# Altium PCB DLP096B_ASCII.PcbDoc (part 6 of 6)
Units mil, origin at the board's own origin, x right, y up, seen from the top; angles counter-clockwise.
Board outline 4950 x 3159.45 mil, 8 copper layers (Top Layer, GND1, SIGNAL1, POWER1, POWER2, SIGNAL2, GND2, Bottom Layer), stack 60.4 mil thick; 327 components, 222 nets, 1374 pads, 853 vias.
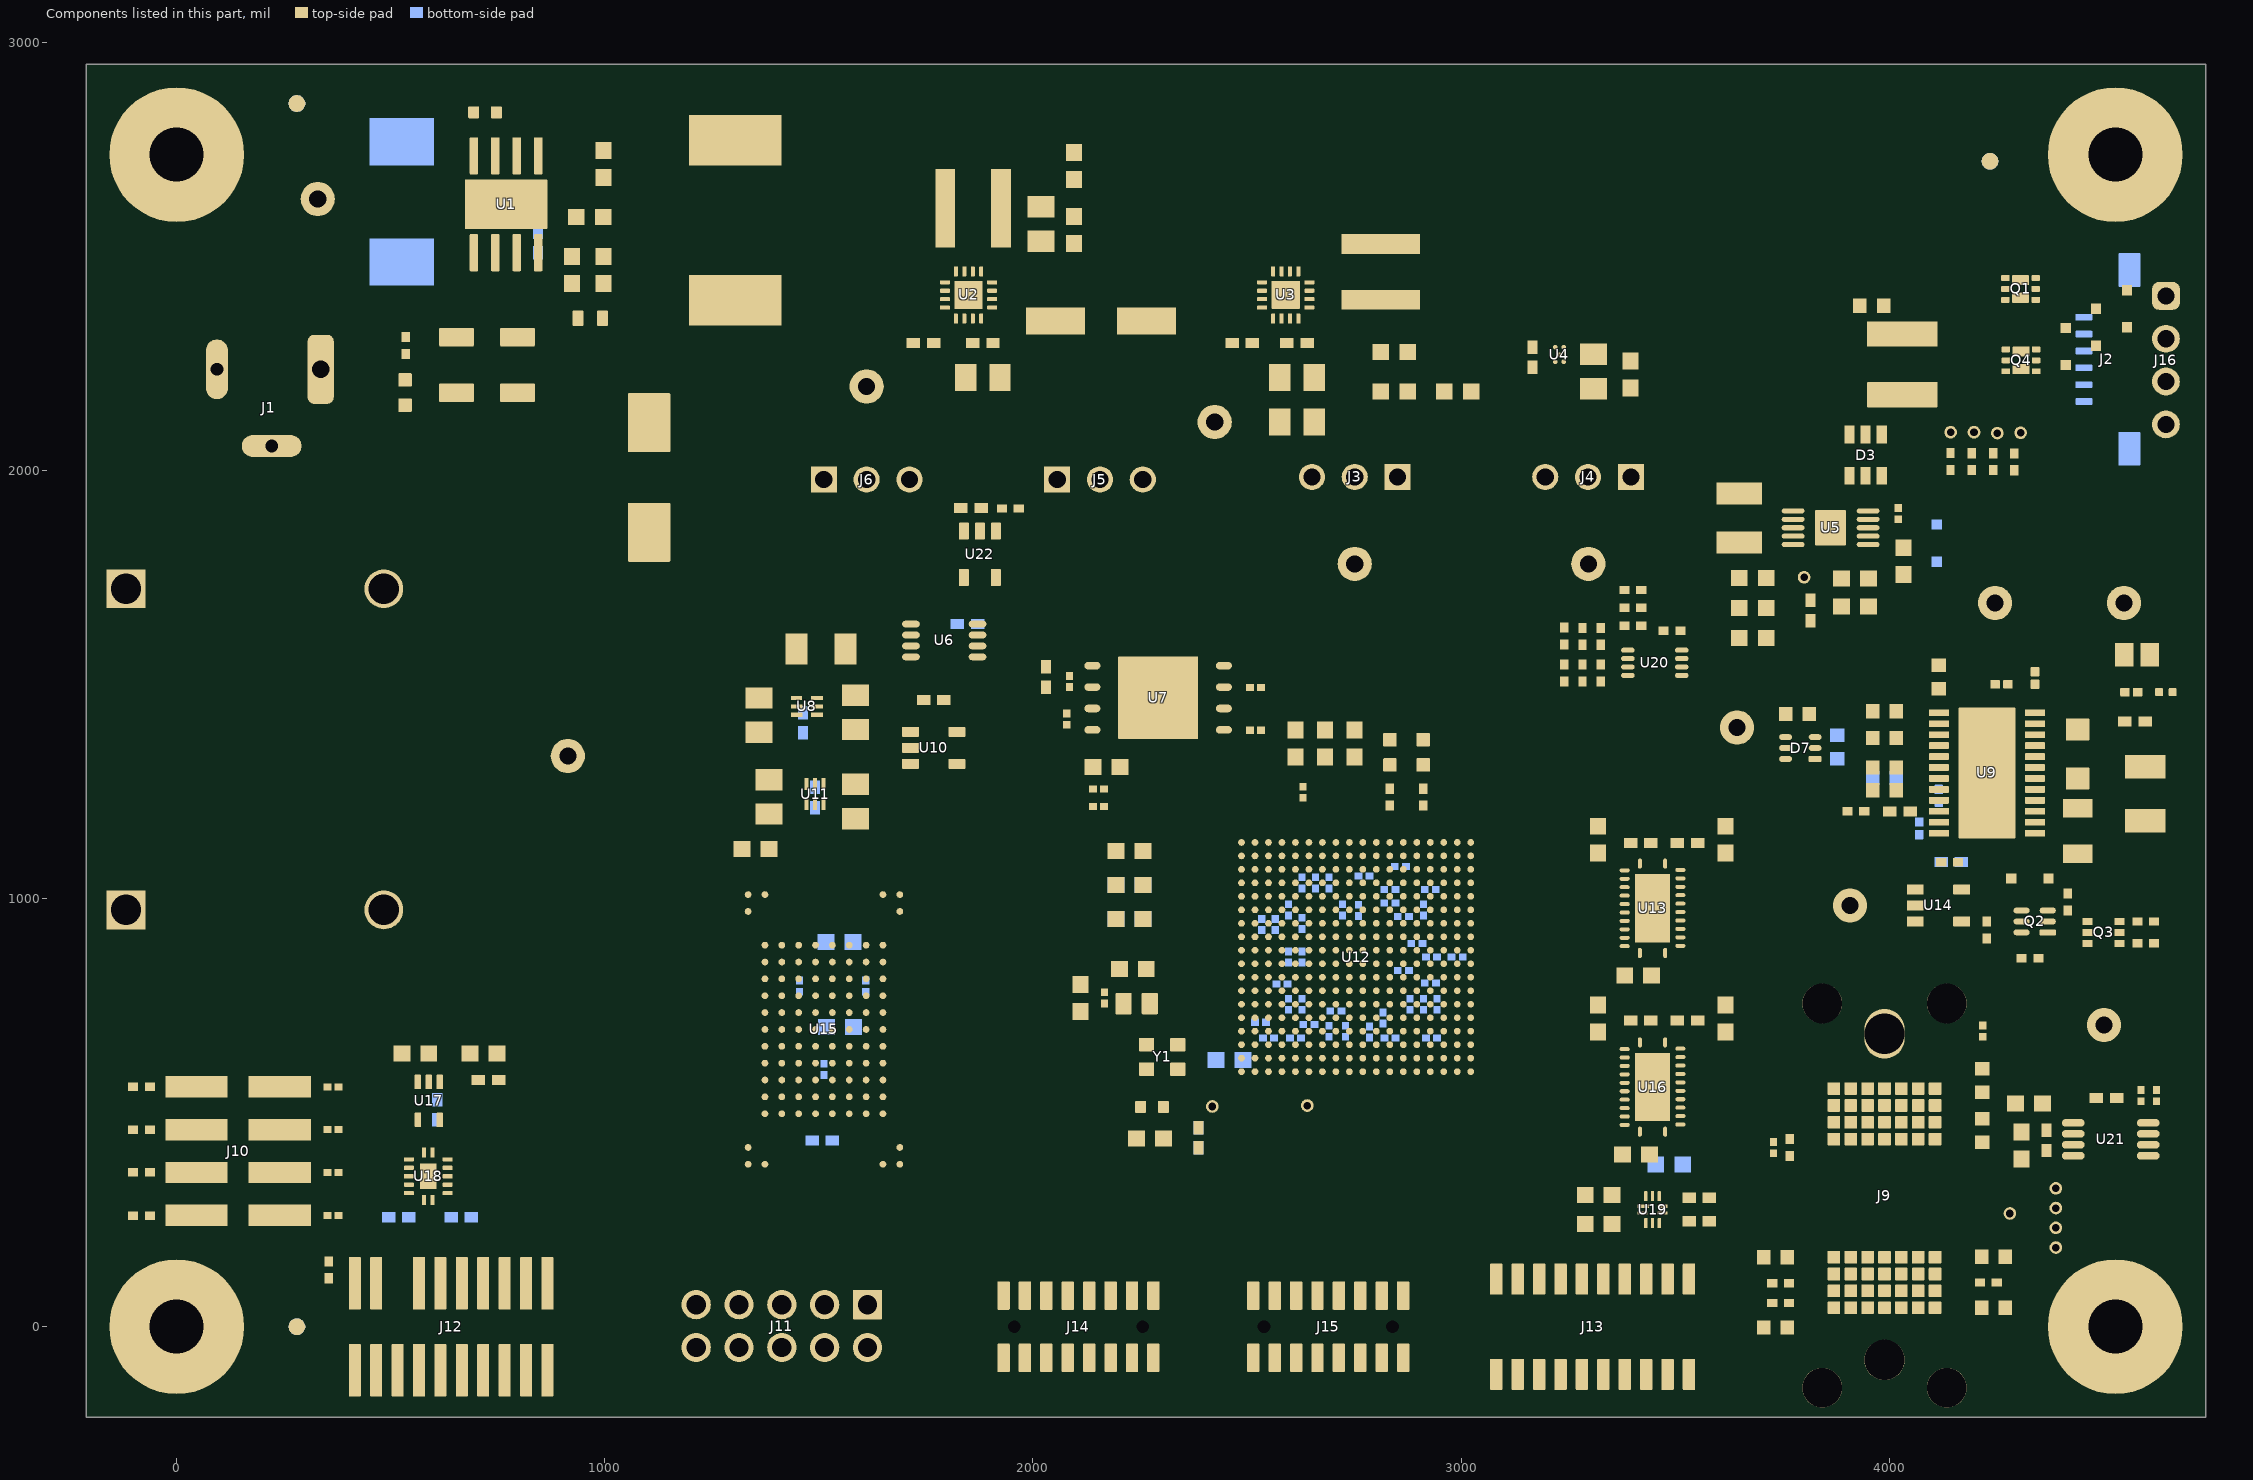
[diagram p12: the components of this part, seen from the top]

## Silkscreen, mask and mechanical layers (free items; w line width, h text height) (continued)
Bottom Overlay:
  circle w6: c814.97,657.14 r30
  circle w6: c2518.15,773.17 r30
  circle w6: c3168.33,1634.16 r35.79
  circle w6: c2810.54,867.54 r35.79
  circle w6: c2940.69,1084.07 r35.79
  circle w6: c3019.28,1758.86 r35.79
  lines w6.1: 1606.15,323.73 1618.25,311.63 2366.59,311.63 2437.83,382.88 2437.83,412.37 ; 1856.23,271.65 1874.92,290.34 2443.32,290.34 2500.02,347.04 ; 2545.44,1479.14 3076.06,1479.14 3076.06,1844.14 2545.44,1844.14 2545.44,1479.14 ; 2763.71,596.69 2763.71,914.6 3028.72,914.6 3028.72,596.69 2763.71,596.69 ; 3113.42,1230.44 3534.9,1230.44 3534.9,1694.31 3113.42,1694.31 3113.42,1230.44
  lines w6.5: 2343.94,907.34 2355.79,895.49 2511.54,895.49 2525.01,908.96 ; 2502.83,674.47 2480.18,697.12 2480.18,841.53 2520.07,881.42 2545.47,906.82 2750.32,906.82 2750.32,715.95 ; 2537.93,657.75 2741.39,657.75 2749.23,665.6 ; 2565.11,1039.03 2607.03,1039.03 ; 2644.27,1124.6 2644.27,1071.06 2648.73,1065.59 ; 759.47,468.68 759.47,973.06 1265.3,973.06 1265.3,468.68 759.47,468.68 ; 2676.36,940.39 2676.36,1131.4 2988.4,1131.4 2988.4,940.39 2676.36,940.39
  text "B" at 3027.97,1744.87 h30
  text "A" at 3178.08,1623.04 h30
  text "B" at 2949.37,1070.08 h30
  text "A" at 2820.32,853.2 h30
  text "C" at 2525.25,758.44 h30
  text "C" at 824.25,642.61 h30
  text ".Layer_Name" at 366,-1069.49 h60
Top Paste:
  text ".Layer_Name" at 366,-1069.49 h60
Bottom Paste:
  text ".Layer_Name" at 366,-1069.49 h60
Top Solder:
  text ".Layer_Name" at 366,-1069.49 h60
  text ".Layer_Name" at 366,-1069.49 h60
Bottom Solder:
  text ".Layer_Name" at 366,-1069.49 h60
Drill Guide:
  text ".Layer_Name" at 366,-1069.49 h60
M1 Board Outline:
  lines w10: -211,-211 -211,2948.45 4739,2948.45 4739,-211 -211,-211
  lines w47.24: -211,-211 -211,2948.45 4739,2948.45 4739,-211 -211,-211 ; 3851.09,217.59 ccw(c3866.84,217.59) 3866.84,201.85 4110.93,201.85 ccw(c4110.93,217.59) 4126.68,217.59 4126.68,382.95 ccw(c4110.93,382.95) 4110.93,398.7 3866.84,398.7 ccw(c3866.84,382.95) 3851.09,382.95 3851.09,217.59
  text "CUTOUT" at 3901.4,248.13 h30
  text ".Layer_Name" at 366,-1069.49 h60
M2 Board Dimensions:
  rectangle: 4839.9,-147.52 4964.9,-22.52
  rectangle: 4964.9,-272.52 5339.9,-147.52
  lines w7: 4839.9,-147.52 5839.9,-147.52 ; 4964.9,-272.52 4964.9,-22.52 ; 5089.9,-272.52 5089.9,-22.52 ; 5339.9,-272.52 5339.9,-22.52 ; 5589.9,-272.52 5589.9,-22.52 ; 4839.9,-272.52 5839.9,-272.52 5839.9,-22.52 4839.9,-22.52 4839.9,-272.52
  lines w10: -211,-211 4739,-211 4739,2948.45 -211,2948.45 -211,-211
M3 3D STEP Top:
  text ".Layer_Name" at 366,-1069.49 h60
M4 3D STEP Bottom:
  text ".Layer_Name" at 366,-1069.49 h60
M5 Assembly Top:
  circle w2: c4143.43,2089.2 r13.63
  circle w2: c4197.91,2089.2 r13.63
  circle w2: c4252.38,2087.15 r13.63
  circle w2: c4306.86,2087.97 r13.63
  circle w5: c693.91,2474.79 r4.82
  circle w10: c1214.61,1009.18 r5.16
  circle w10: c2428.46,1372.93 r12.89
  circle w10: c2438.83,1131.11 r5.45
  circle w10: c1750.3,1396.72 r2.8
  circle w10: c2289.22,-44.55 r10.59
  circle w10: c2872.18,-44.05 r11.92
  circle w10: c3870.88,662.49 r4.25
  circle w10: c3537.37,-76.24 r13.63
  circle w10: c4093.94,1029.87 r1.85
  circle w10: c4354.39,918.45 r2.33
  circle w10: c3219.35,2288.22 r1.33
  circle w10: c-65,2457.17 r12.26
  circle w10: c620.97,544.94 r1.81
  circle w10: c598.22,302.19 r1.63
  circle w10: c220.03,260.82 r8.63
  circle w10: c415.01,-72.87 r11.68
  rectangle: 3371.78,1959.73 3424.57,2010.65
  rectangle: 2827.38,1960.2 2880.16,2011.12
  rectangle: 2029.75,1954.35 2082.54,2005.27
  rectangle: 1484.75,1954.35 1537.54,2005.27
  lines w5: 3204.84,2239.53 3204.84,2302.05 3254.46,2302.05 3254.46,2239.53 3204.84,2239.53
  lines w6.1: 5590.34,2153.55 6590.58,2153.55 ; 5590.34,2228.55 6591.41,2228.55 ; 5590.34,2303.55 6591.41,2303.55 ; 5590.34,2378.55 6591.28,2378.55 ; 5590.34,2453.55 6590.17,2453.55 ; 5946.27,2078.55 5946.27,2553.55 ; 5590.34,2078.55 5590.34,2553.55 6592.35,2553.55 6592.35,2078.55 5590.34,2078.55
  lines w6.5: 681.08,2462.25 681.08,2780.49 859.41,2780.49 859.41,2462.25 681.08,2462.25
  lines w10: -503,-1141.17 6097,-1141.17 ; -503,-937.83 6099,-937.83 ; -503,-734.5 -503,-1344.5 3502,-1344.5 6099,-1344.5 6099,-734.5 -502.5,-734.5 -502.5,-1344.5 1073,-1344.5 ; 1962,-1344.5 1962,-734.5 ; 3229,-937.83 3229,-734.5 ; 3809.41,1321.42 cw(c3808.6,1321.42) 3809.39,1321.62 ; 4069,-937.83 4069,-734.5 ; 4691,-1351 4691,-1148.17
  text "U1" at 756.26,2613.87 h20
  text "Jumper stuff list table for DLP2021Q1PRU-DVH" at 5477.66,2603.4 h30
  text "Ref Des" at 5653.13,2489.39 h35
  text "Position" at 6142.56,2489.39 h35
  text "J3" at 5741.85,2399.68 h30
  text "1-2" at 6230.44,2399.68 h30
  text "K" at 4139.37,2361.8 h20
  text "J4" at 5741.85,2324.68 h30
  text "1-2" at 6230.44,2324.68 h30
  text "J5" at 5741.85,2249.68 h30
  text "1-2" at 6230.44,2249.68 h30
  text "+" at 1084.14,2198.94 h60
  text "J6" at 5741.85,2174.68 h30
  text "1-2" at 6230.44,2174.68 h30
  text "K" at 526.21,2120.34 h20
  text "TP3" at 4200.88,2114.16 h20 r90
  text "TP14" at 4286.8,2112.81 h20 r90
  text "TP15" at 4245.96,2111.95 h20 r90
  text "TP2" at 4162.06,2109.31 h20 r90
  text "1-2, 3-4, 5-6, 7-8" at 6005.52,2103.01 h30
  text "J10" at 5729.36,2099.68 h30
  text "K" at 4435.38,1431.31 h20
  text "K" at 2827.81,1380.59 h20
  text "K" at 2905,1379.47 h20
  text "K" at 4224.96,1035.44 h20
  text "COMPONENTS MARKED 'DNP' SHOULD NOT BE POPULATED." at 942.5,-529.5 h60
  text "ASSEMBLY VARIANT:" at 942,-645 h60
  text ".VariantName" at 1978,-645 h60
  text "PCB VIEWED FROM TOP SIDE" at -439.5,-866.67 h60
  text "BOARD #:" at 2037,-866.67 h60
  text ".PRJ_Number" at 2582.5,-866.67 h60
  text "REV:" at 3427,-866.67 h60
  text ".PCB_Rev" at 3718.5,-866.67 h60
  text "SVN REV:" at 4265,-866.67 h60
  text ".VersionControl_RevNumber" at 4771,-866.67 h60
  text "TID #:" at 2037,-1070 h60
  text ".TID" at 2582.5,-1070 h60
  text "PLOT NAME =" at -439.5,-1275.34 h60
  text ".plot_File_Name" at 366,-1275.34 h60
  text "GENERATED    :" at 2039,-1275.34 h60
  text ".Print_Date" at 2908.5,-1275.34 h60
  text ".Print_Time" at 3637.5,-1275.34 h60
  text "TEXAS INSTRUMENTS" at 4902,-1275.34 h60
M6 Assembly Bottom:
  lines w10: -503.5,-938.33 6098.5,-938.33 ; -501.5,-1141.67 6098.5,-1141.67 ; 904.5,-1351.5 904.5,-1148.67 ; 1526.5,-938.33 1526.5,-735 ; 2366.5,-938.33 2366.5,-735 ; 3633.5,-1345 3633.5,-735 ; 4522.5,-1345 6098,-1345 6098,-735 -503.5,-735 -503.5,-1345 2093.5,-1345 6098.5,-1345 6098.5,-735
  text "COMPONENTS MARKED 'DNP' SHOULD NOT BE POPULATED." at 5891,-529 h60
  text ".VariantName" at 4847,-645 h60
  text "ASSEMBLY VARIANT:" at 5886,-645 h60
  text ".VersionControl_RevNumber" at 824.5,-867.17 h60
  text "SVN REV:" at 1330.5,-867.17 h60
  text ".PCB_Rev" at 1877,-867.17 h60
  text "REV:" at 2168.5,-867.17 h60
  text ".PRJ_Number" at 3013,-867.17 h60
  text "BOARD #:" at 3558.5,-867.17 h60
  text "PCB VIEWED FROM BOTTOM SIDE" at 6035,-867.17 h60
  text ".TID" at 3013,-1070.5 h60
  text "TID #:" at 3558.5,-1070.5 h60
  text "TEXAS INSTRUMENTS" at 693.5,-1275.84 h60
  text ".Print_Time" at 1958,-1275.84 h60
  text ".Print_Date" at 2687,-1275.84 h60
  text "GENERATED    :" at 3556.5,-1275.84 h60
  text ".plot_File_Name" at 5229.5,-1275.84 h60
  text "PLOT NAME =" at 6035,-1275.84 h60
M9 Title Sheet:
  lines w10: -702.5,830.5 -502.5,830.5 ; -702.5,3205.5 -502.5,3205.5 ; -702.5,5580.5 -502.5,5580.5 ; 1797.5,-1544.5 1797.5,-1344.5 ; 1797.5,7755.5 1797.5,7955.5 ; 4297.5,-1544.5 4297.5,-1344.5 ; 4297.5,7755.5 4297.5,7955.5 ; 6110,-1344.5 6110,-734.5 11092.5,-734.5 ; 6797.5,-1544.5 6797.5,-1344.5 ; 6797.5,7755.5 6797.5,7955.5 ; 9297.5,-1544.5 9297.5,-1344.5 ; 9297.5,7755.5 9297.5,7955.5 ; 11092.5,-1344.5 11092.5,-734.5 ; 11092.5,-1034.5 14092.5,-1034.5 ; 11092.5,-434.5 14092.5,-434.5 ; 11093.5,159.5 14093.5,159.5 ; 11797.5,-1544.5 11797.5,-1344.5 ; 11797.5,7755.5 11797.5,7955.5 ; 12597.5,-1334.5 12597.5,-734.5 ; 14092.5,-734.5 11092.5,-734.5 ; 14092.5,-134.5 11092.5,-134.5 ; 14097.5,-144.5 14097.5,-1344.5 ; 14097.5,660 11093.5,660 11092.5,660 11092.5,159.5 11092.5,-134.5 ; 14097.5,830.5 14297.5,830.5 ; 14097.5,3205.5 14297.5,3205.5 ; 14097.5,5580.5 14297.5,5580.5 ; 11092.5,-734.5 11092.5,-134.5 ; 14097.5,-1344.5 14097.5,7755.5 -502.5,7755.5 -502.5,-1344.5 14097.5,-1344.5 ; -702.5,-1544.5 -702.5,7955.5 14297.5,7955.5 14297.5,-1544.5 -702.5,-1544.5
  text "1" at 528.84,7825.5 h70
  text "2" at 3024.5,7825.5 h70
  text "3" at 5513.84,7825.5 h70
  text "4" at 8020.51,7825.5 h70
  text "5" at 10519.5,7825.5 h70
  text "6" at 13024.5,7825.5 h70
  text "A" at -627.5,6682.5 h70
  text "A" at 14172.5,6682.5 h70
  text "B" at -627.5,4302.5 h70
  text "B" at 14172.5,4302.5 h70
  text "C" at -627.5,1927.5 h70
  text "C" at 14172.5,1927.5 h70
  text "PROJECT TITLE:" at 11132.5,66.5 h45
  text ".PRJ_Title" at 11182.5,-66.83 h70
  text "DESIGNED FOR:" at 11132.5,-234.5 h45
  text ".PRJ_Customer" at 11182.5,-374.5 h70
  text "D" at -627.5,-442.5 h70
  text "D" at 14172.5,-442.5 h70
  text "FILE NAME:" at 11132.5,-534.5 h45
  text ".PCB_File_Name_No_Path" at 11182.5,-654.5 h70
  text "Texas Instruments (TI) and/or its licensors do not warrant the accuracy or completeness of this specification" at 6163,-816.34 h45
  text "ENGINEER:" at 11132.5,-824.5 h45
  text "LAYOUT BY:" at 12637.5,-824.5 h45
  text "or any information contained therein. TI and/or its licensors do not warrant that this design will meet" at 6118.01,-929 h45
  text ".PRJ_Engineer" at 11182.5,-979.49 h70
  text ".PCB_Layout" at 12688,-979.49 h70
  text "the specifications, will be suitable for your application or fit for any particular purpose, or will operate in" at 6118.01,-1041.67 h45
  text "ALTIUM DESIGNER VERSION:" at 12637.5,-1134.5 h45
  text "an implementation. TI and/or its licensors do not warrant that the design is production worthy. You should" at 6118.01,-1154.33 h45
  text "completely validate and test your design implementation to confirm the system functionality for your application." at 6163,-1267 h45
  text ".print_Scale" at 11182.5,-1267.83 h70
  text ".Application_BuildNumber" at 12688,-1267.83 h70
  text "1" at 528.84,-1474.5 h70
  text "2" at 3024.5,-1474.5 h70
  text "3" at 5513.84,-1474.5 h70
  text "4" at 8020.51,-1474.5 h70
  text "5" at 10519.5,-1474.5 h70
  text "6" at 12065.46,-1480.85 h70
  text "WO# : 309481 - 9479-D" at 12561.41,-1481.02 h70
M10 Fab Notes:
  drawing of 203 lines, arcs and shapes, not listed
  text "FAB NOTES :" at -262.62,7503.09 h80
  text "1.  BOARD DIMENSION : 125.73MM X 80.25MM." at -105.99,7237.15 h80
  text "2. VENDOR MAY ADJUST SOLDERMASK WHEREVER SOLDERMASK PADS ARE THE SAME SIZE (1:1) AS PER THE MANUFACTURING CAPABILITIES AND" at -102.63,7001.58 h80
  text "ALL OTHER SOLDER MASK PADS SHALL NOT BE MODIFIED, PROVIDED NO ADJACENT COPPER IS EXPOSED AND NO CONFLICT IS PRODUCED WITH ANY STATED \"VIA TENTING/COVERING\" REQUIREMENTS." at 129.91,6836.27 h80
  text "3. ALL VIAS ARE TENTED ON BOTH SIDES UNLESS OTHERWISE SOLDER MASK IS OPENED IN GERBER." at -102.63,6661.33 h80
  text "4. TRACES WITH 6.5MIL TO BE 50 OHMS +/-10% SINGLE ENDED ON TOP LAYER, SIGNAL1, SIGNAL2 & BOTTOM LAYER (L1,L3,L6 & L8)." at -102.63,6483.62 h80
  text "5. 8.02MIL VIAS NEED TO BE FILLED WITH NON-CONDUCTIVE EPOXY-RESIN AND OVERPLATE WITH COPPER. SURFACE MUST BE FLAT," at -100.72,6269.39 h80
  text "DESIGN INFORMATION" at 12171.02,6145.17 h60
  text "FLATNESS TOLERANCE IS +0.000/-0.001\" ON TOP SIDE ONLY AND +0.000/-0.003\" ON BOTTOM SIDE." at 136.97,6078.42 h80
  text "MIN. TRACK WIDTH:" at 11526.46,6013.05 h60
  text "5" at 12622.7,6013.05 h60
  text "MIL" at 12777.46,6013.05 h60
  text "MINIMUM ANNULAR RING REQUIREMENT IS WAIVED FOR FILLED VIAS." at 133.68,5906.93 h80
  text "5" at 12619.35,5895.9 h60
  text "MIN. CLEARANCE:" at 11526.46,5888.92 h60
  text "MIL" at 12777.46,5888.92 h60
  text "19.685" at 12425.36,5767.1 h60
  text "MIN. VIA PAD SIZE:" at 11526.46,5764.8 h60
  text "MIL" at 12777.46,5764.8 h60
  text "6. 8.01MIL VIAS NEED TO BE FILLED WITH NON-CONDUCTIVE EPOXY-RESIN AND OVERPLATE WITH COPPER. SURFACE MUST BE FLAT," at -92.06,5714.26 h80
  text "0.05mm (2MIL)" at 12221.46,5634.9 h60
  text "MINIMUM ANNULAR RING" at 11197.23,5626.67 h60
  text "EXTERNAL" at 12929.46,5626.67 h60
  text "FLATNESS TOLERANCE IS +0.000/-0.001\" ON BOTTOM SIDE ONLY AND +0.000/-0.003\" ON TOP SIDE." at 143.57,5524.37 h80
  text "PER" at 11397.23,5516.55 h60
  text "IPC-D-275 CLASS 2 LEVEL C" at 11617.23,5516.54 h60
  text "MIL, HOLES" at 13105.46,5416.07 h60
  text "+/-" at 12713,5407.48 h60
  text "+/-" at 13567,5407.48 h60
  text "REGISTRATION TOLERANCES:" at 11197.23,5406.42 h60
  text "METAL" at 12397,5406.42 h60
  text "5" at 12973.2,5406.42 h60
  text "3" at 13806.2,5406.42 h60
  text "MIL" at 13922.46,5406.42 h60
  text "MINIMUM ANNULAR RING REQUIREMENT IS WAIVED FOR FILLED VIAS." at 143.57,5349.58 h80
  text "HOLE SIZE TOLERANCE (UNLESS OTHERWISE SPECIFIED):" at 11197.23,5308.1 h60
  text "+/-" at 13567,5305.23 h60
  text "3" at 13806.2,5304.17 h60
  text "MIL" at 13922.46,5304.17 h60
  text "MATERIAL:" at 11122.46,5166.52 h60
  text "FR-4 High Tg" at 12108.9,5038 h60
  text "X" at 11964.46,5030.01 h60
  text "FR-408" at 11543.46,5025.49 h60
  text "OTHER" at 13031.46,5025.49 h60
  text "62 MIL (1.6mm) +/-10%" at 11863.56,4882.46 h60
  text "X" at 11743.46,4880.01 h60
  text "THICKNESS:" at 11197.23,4874.24 h60
  text "OTHER" at 13148.46,4874.24 h60
  text "TOLERANCE:" at 11197.23,4735.92 h60
  text "X" at 12045.46,4735.92 h60
  text "ANSI IPC-6012 TYPE 3 CLASS 2" at 12223.48,4735.92 h60
  text "OTHER +/-" at 12223.46,4591.73 h60
  text "BOW & TWIST:" at 11197.23,4446.54 h60
  text "X" at 12045.46,4446.54 h60
  text "ANSI IPC-6012 TYPE 3 CLASS 2" at 12223.48,4446.54 h60
  text "OTHER +/-" at 12223.46,4299.85 h60
  text "DRILLING:" at 11122.46,4169.23 h60
  text "NC_DRILL FILES" at 12883.46,4064.04 h60
  text "REFERENCE:" at 11197.23,4060.1 h60
  text "X" at 11854.46,4060.01 h60
  text "AS SHOWN" at 12032.46,4060.1 h60
  text "X" at 12755.46,4060.1 h60
  text "OTHER" at 13181.46,3917.85 h60
  text "PTH COPPER THICKNESS:" at 11196.91,3914.32 h60
  text "X" at 12336.14,3914.32 h60
  text "20-30 um" at 12464.14,3914.32 h60
  text "BOARD FINISH:" at 11122.46,3766.73 h60
  text "SILKSCREEN:" at 11277.68,3656.6 h60
  text "X" at 12235.46,3656.6 h60
  text "TOP" at 12352.46,3656.6 h60
  text "X" at 12745.46,3656.6 h60
  text "BOTTOM" at 12863.46,3656.6 h60
  text "SILKSCREEN COLOR:" at 11277.68,3501.41 h60
  text "X" at 12234.46,3501.41 h60
  text "WHITE" at 12352.46,3501.41 h60
  text "OTHER" at 12863.46,3501.41 h60
  text "X" at 12365.46,3357.96 h60
  text "GREEN" at 12483.46,3357.96 h60
  text "OTHER" at 13101.46,3357.96 h60
  text "SOLDER RESIST COLOR:" at 11277.68,3351.1 h60
  text "X" at 12957.46,3205.23 h60
  text "MATTE" at 12483.46,3203.71 h60
  text "SEMI-GLOSS" at 13101,3203.07 h60
  text "IMMERSION GOLD (ENIG)" at 12183.46,3030.94 h60
  text "ENEPIG" at 13521,3023.72 h60
  text "SURFACE FINISH:" at 11122.46,3022.72 h60
  text "X" at 12005.46,3022.72 h60
  text "IMM. TIN/SILVER OR EQUIV" at 11452,2885.4 h60
  text "OTHER" at 12883.46,2881.47 h60
  text "ARRAY/PANEL:" at 11122.46,2726.09 h60
  text "CUT AND TRIM PER M1 BOARD OUTLINE" at 12183.46,2717.87 h60
  text "N.C. ROUTE" at 12183.46,2581.9 h60
  text "X" at 12871.46,2581.9 h60
  text "V. SCORE" at 13049.46,2581.9 h60
  text "CERTIFICATION:" at 11122.46,2452.77 h60
  text "MATERIALS AND WORKMANSHIP FOR ALL PCBS" at 11847.46,2452.77 h60
  text "TO MEET OR EXCEED THE REQUIREMENTS OF:" at 11847.46,2358.71 h60
  text "X" at 11484.97,2230.08 h60
  text "ANSI IPC-A-600F CLASS ->" at 11612.96,2230.08 h60
  text "X" at 13260.97,2230.08 h60
  text "2" at 13370.96,2230.08 h60
  text "1" at 13055.96,2228.58 h60
  text "3" at 13724.96,2228.58 h60
  text "X" at 12296.97,2082.39 h60
  text "RoHS" at 12424.96,2082.39 h60
  text "OTHER" at 13069.36,2082.39 h60
  text "PER ORDER" at 13466.42,2082.39 h60
  text "ALL BOARDS MUST MEET OR EXCEED UL94-V0 REQUIREMENTS." at 11150,1928.57 h60
  text "PCB MUST BEAR THE UL94V-0 UL REGISTERED MATERIAL ID NUMBER" at 11150,1812.5 h60
  text "ADDITIONAL REQUIREMENTS:" at 11122.46,1643.08 h60
  text "MICROSECTION:" at 11197.23,1535.95 h60
  text "YES" at 12102.96,1535.95 h60
  text "REQUIRED" at 12964.46,1391.62 h60
  text "BARE BOARD ELEC. TEST:" at 11197.23,1388.76 h60
  text "NONE" at 12502.96,1388.76 h60
  text "X" at 12846.46,1388.76 h60
  text "PER ORDER" at 13556.46,1388.76 h60
  text "XX MIL VIAS REQUIRE NON-CONDUCTIVE FILL AND PLANARIZE" at 11365.38,1183.82 h59
  text "XX MIL VIAS REQUIRE CONDUCTIVE FILL AND PLANARIZE" at 11373.38,1079.84 h60
  text "OUTER XX MIL TRACES REQUIRE 50 OHM SINGLE-ENDED IMPEDANCE" at 11372.39,916.46 h58
  text "LAYER 2 & 3 (INNER LAYERS) XX MIL WIDE, XX MIL SPACE / TRACES REQUIRE 100 OHM DIFFERENTIAL IMPEDANCE" at 11364.39,680.74 h60
M11 Gerber Information:
  lines w10: -503,-1141.17 6097,-1141.17 ; -503,-937.83 6099,-937.83 ; -503,-734.5 -503,-1344.5 3502,-1344.5 6099,-1344.5 6099,-734.5 -502.5,-734.5 -502.5,-1344.5 1073,-1344.5 ; 1962,-1344.5 1962,-734.5 ; 3229,-937.83 3229,-734.5 ; 4069,-937.83 4069,-734.5 ; 4691,-1351 4691,-1148.17
  text "ALL ARTWORK VIEWED FROM TOP SIDE" at -439.5,-866.67 h60
  text "BOARD #:" at 2037,-866.67 h60
  text ".PRJ_Number" at 2582.5,-866.67 h60
  text "REV:" at 3427,-866.67 h60
  text ".PCB_Rev" at 3718.5,-866.67 h60
  text "SVN REV:" at 4265,-866.67 h60
  text ".VersionControl_RevNumber" at 4771,-866.67 h60
  text "LAYER NAME =" at -439.5,-1069.49 h60
  text "TID #:" at 2037,-1070 h60
  text ".TID" at 2582.5,-1070 h60
  text "PLOT NAME =" at -439.5,-1275.34 h60
  text ".plot_File_Name" at 366,-1275.34 h60
  text "GENERATED    :" at 2039,-1275.34 h60
  text ".Print_Date" at 2908.5,-1275.34 h60
  text ".Print_Time" at 3637.5,-1275.34 h60
  text "TEXAS INSTRUMENTS" at 4902,-1275.34 h60
M12 Stackup:
  drawing of 521 lines, arcs and shapes, not listed
  text "LAYER STACK-UP :" at 5845.47,5245.68 h80
  text "Layer" at 5895.54,4957.06 h55
  text "Name" at 6272.96,4957.06 h55
  text "Material" at 7126.89,4957.06 h55
  text "Thickness" at 7916.67,4957.06 h55
  text "Constant" at 8514.02,4957.06 h55
  text "Board Layer Stack" at 9038.06,4957.06 h55
  text "Top Overlay" at 6272.96,4847.06 h55
  text "Top Solder" at 6272.96,4737.06 h55
  text "Solder Resist" at 7126.89,4737.06 h55
  text "0.80mil" at 7916.67,4737.06 h55
  text "3.5" at 8514.02,4737.06 h55
  text "4" at 5725.88,4686 h60
  text "1" at 5895.54,4627.06 h55
  text "Top Layer" at 6272.96,4627.06 h55
  text "2.80mil" at 7916.67,4627.06 h55
  text "Dielectric 1" at 6272.96,4517.06 h55
  text "FR-4 High Tg" at 7126.89,4517.06 h55
  text "4.00mil" at 7916.67,4517.06 h55
  text "4.1" at 8514.02,4517.06 h55
  text "2" at 5895.54,4407.06 h55
  text "GND1" at 6272.96,4407.06 h55
  text "CF-004" at 7126.89,4407.06 h55
  text "1.40mil" at 7916.67,4407.06 h55
  text "Dielectric 2" at 6272.96,4297.06 h55
  text "FR-4 High Tg" at 7126.89,4297.06 h55
  text "8.00mil" at 7916.67,4297.06 h55
  text "4.1" at 8514.02,4297.06 h55
  text "4" at 5729.83,4246.99 h60
  text "3" at 5895.54,4187.06 h55
  text "SIGNAL1" at 6272.96,4187.06 h55
  text "CF-004" at 7126.89,4187.06 h55
  text "1.40mil" at 7916.67,4187.06 h55
  text "Dielectric 3" at 6272.96,4077.06 h55
  text "FR-4 High Tg" at 7126.89,4077.06 h55
  text "8.00mil" at 7916.67,4077.06 h55
  text "4.1" at 8514.02,4077.06 h55
  text "4" at 5895.54,3967.06 h55
  text "POWER1" at 6272.96,3967.06 h55
  text "CF-004" at 7126.89,3967.06 h55
  text "1.40mil" at 7916.67,3967.06 h55
  text "Dielectric 4" at 6272.96,3857.06 h55
  text "FR-4 High Tg" at 7126.89,3857.06 h55
  text "6.40mil" at 7916.67,3857.06 h55
  text "4.8" at 8514.02,3857.06 h55
  text "5" at 5895.54,3747.06 h55
  text "POWER2" at 6272.96,3747.06 h55
  text "CF-004" at 7126.89,3747.06 h55
  text "1.40mil" at 7916.67,3747.06 h55
  text "Dielectric 5" at 6272.96,3637.06 h55
  text "FR-4 High Tg" at 7126.89,3637.06 h55
  text "8.00mil" at 7916.67,3637.06 h55
  text "4.1" at 8514.02,3637.06 h55
  text "4" at 5731.44,3592.36 h60
  text "6" at 5895.54,3527.06 h55
  text "SIGNAL2" at 6272.96,3527.06 h55
  text "CF-004" at 7126.89,3527.06 h55
  text "1.40mil" at 7916.67,3527.06 h55
  text "Dielectric 6" at 6272.96,3417.06 h55
  text "FR-4 High Tg" at 7126.89,3417.06 h55
  text "8.00mil" at 7916.67,3417.06 h55
  text "4.1" at 8514.02,3417.06 h55
  text "7" at 5895.54,3307.06 h55
  text "GND2" at 6272.96,3307.06 h55
  text "CF-004" at 7126.89,3307.06 h55
  text "1.40mil" at 7916.67,3307.06 h55
  text "Dielectric 7" at 6272.96,3197.06 h55
  text "FR-4 High Tg" at 7126.89,3197.06 h55
  text "4.00mil" at 7916.67,3197.06 h55
  text "4.1" at 8514.02,3197.06 h55
  text "4" at 5728.68,3143.87 h60
  text "8" at 5895.54,3087.06 h55
  text "Bottom Layer" at 6272.96,3087.06 h55
  text "2.80mil" at 7916.67,3087.06 h55
  text "Bottom Solder" at 6272.96,2977.06 h55
  text "Solder Resist" at 7126.89,2977.06 h55
  text "0.80mil" at 7916.67,2977.06 h55
  text "3.5" at 8514.02,2977.06 h55
  text "Bottom Overlay" at 6272.96,2867.06 h55
  text "THIS IS AN IMPEDANCE CONTROLLED BOARD." at 6405.68,2676.09 h80
  text "NOTE :" at 5399.78,2633.46 h80
  text "1. ALL CORE AND PREPREG THICKNESSES ARE UP TO FAB SHOP TO SELECT." at 5410.27,2418.37 h80
  text "2. EXTERNAL LAYER CU THICKNESSES ARE FINISHED THICKNESS AFTER PLATING." at 5410.27,2212.01 h80
M13 Component Bodies Top:
  text ".Layer_Name" at 366,-1069.49 h60
M14 Component Bodies Bottom:
  text ".Layer_Name" at 366,-1069.49 h60
M15 Courtyards Top:
  text ".Layer_Name" at 366,-1069.49 h60
M16 Courtyards Bottom:
  text ".Layer_Name" at 366,-1069.49 h60
Drill Drawing:
  circle w10: c6205.2,289.86 r27.63
  lines w10: 5999.71,1326.4 6095.41,1326.4 6095.41,1417.96 5999.71,1417.96 5999.71,1326.4 ; 6001.12,1191.74 6096.82,1191.74 6096.82,1286.73 6001.12,1286.73 6001.12,1191.74 ; 6177.58,151.73 6191.39,151.73 6205.2,137.91 6219.02,151.73 6232.83,151.73 6219.02,165.54 6232.83,179.35 6219.02,179.35 6205.2,193.17 6191.39,179.35 6177.58,179.35 6191.39,165.54 6177.58,151.73 ; 6177.58,690.45 6232.83,690.45 6205.2,635.19 6177.58,690.45 ; 6177.58,1008.15 6232.83,1008.15 6232.83,1063.41 6177.58,1063.41 6177.58,1008.15
  lines w12: 6127.49,-520.98 10811.82,-520.98 ; 6127.49,1716.78 10811.82,1716.78 ; 6465.35,-645.3 6465.35,1841.1 ; 6797.35,-645.3 6797.35,1841.1 ; 7433.91,-645.3 7433.91,1841.1 ; 7693.05,-645.3 7693.05,1841.1 ; 8068.21,-645.3 8068.21,1841.1 ; 8792.54,-645.3 8792.54,1841.1 ; 9382.45,-645.3 9382.45,1841.1 ; 10059.97,-645.3 10059.97,1841.1 ; 6127.49,-645.3 10811.82,-645.3 10811.82,1841.1 6127.49,1841.1 6127.49,-645.3
  text "DRILL TABLE:" at 6129.79,1884.32 h80
  text "Symbol" at 6202.08,1754.07 h72
  text "Quantity" at 6502.64,1754.07 h72
  text "Finished Hole Size" at 6834.64,1754.07 h72
  text "Plated" at 7471.21,1754.07 h72
  text "Hole Type" at 7730.35,1754.07 h72
  text "Drill Layer Pair" at 8105.51,1754.07 h72
  text "Hole Length" at 8829.84,1754.07 h72
  text "Routed Path Length" at 9419.75,1754.07 h72
  text "Hole Tolerance (Mils)" at 10097.27,1754.07 h72
  text "43" at 6502.64,1629.75 h60
  text "7.87mil (0.200mm)" at 6834.64,1629.75 h60
  text "PTH" at 7471.21,1629.75 h60
  text "Round" at 7730.35,1629.75 h60
  text "Top Layer - Bottom Layer" at 8105.51,1629.75 h60
  text "-" at 8829.84,1629.75 h60
  text "-" at 9419.75,1629.75 h60
  text "+0.00/-7.874" at 10097.27,1629.75 h60
  text "A" at 6176.79,1619.76 h55.25
  text "126" at 6502.64,1505.43 h60
  text "8.00mil (0.203mm)" at 6834.64,1505.43 h60
  text "PTH" at 7471.21,1505.43 h60
  text "Round" at 7730.35,1505.43 h60
  text "Top Layer - Bottom Layer" at 8105.51,1505.43 h60
  text "-" at 8829.84,1505.43 h60
  text "-" at 9419.75,1505.43 h60
  text "+0.00/-8.00" at 10097.27,1505.43 h60
  text "C" at 6176.79,1495.44 h55.25
  text "63" at 6502.64,1381.11 h60
  text "8.01mil (0.203mm)" at 6834.64,1381.11 h60
  text "PTH" at 7471.21,1381.11 h60
  text "Round" at 7730.35,1381.11 h60
  text "Top Layer - Bottom Layer" at 8105.51,1381.11 h60
  text "-" at 8829.84,1381.11 h60
  text "-" at 9419.75,1381.11 h60
  text "+0.00/-8.01" at 10097.27,1381.11 h60
  text "D" at 6176.79,1371.12 h55.25
  text "6" at 6025.98,1348.47 h55
  text "22" at 6502.64,1256.79 h60
  text "8.02mil (0.204mm)" at 6834.64,1256.79 h60
  text "PTH" at 7471.21,1256.79 h60
  text "Round" at 7730.35,1256.79 h60
  text "Top Layer - Bottom Layer" at 8105.51,1256.79 h60
  text "-" at 8829.84,1256.79 h60
  text "-" at 9419.75,1256.79 h60
  text "+0.00/-8.02" at 10097.27,1256.79 h60
  text "B" at 6176.79,1246.8 h55.25
  text "5" at 6031.35,1213.23 h55
  text "593" at 6502.64,1132.47 h60
  text "10.00mil (0.254mm)" at 6834.64,1132.47 h60
  text "PTH" at 7471.21,1132.47 h60
  text "Round" at 7730.35,1132.47 h60
  text "Top Layer - Bottom Layer" at 8105.51,1132.47 h60
  text "-" at 8829.84,1132.47 h60
  text "-" at 9419.75,1132.47 h60
  text "+0.00/-10.00" at 10097.27,1132.47 h60
  text "E" at 6176.79,1122.48 h55.25
  text "6" at 6502.64,1008.15 h60
  text "12.99mil (0.330mm)" at 6834.64,1008.15 h60
  text "PTH" at 7471.21,1008.15 h60
  text "Round" at 7730.35,1008.15 h60
  text "Top Layer - Bottom Layer" at 8105.51,1008.15 h60
  text "-" at 8829.84,1008.15 h60
  text "-" at 9419.75,1008.15 h60
  text "12" at 6502.64,883.83 h60
  text "17.72mil (0.450mm)" at 6834.64,883.83 h60
  text "PTH" at 7471.21,883.83 h60
  text "Round" at 7730.35,883.83 h60
  text "Top Layer - Bottom Layer" at 8105.51,883.83 h60
  text "-" at 8829.84,883.83 h60
  text "-" at 9419.75,883.83 h60
  text "+/-3.00" at 10097.27,883.83 h60
  text "F" at 6176.79,873.84 h55.25
  text "4" at 6502.64,759.51 h60
  text "29.92mil (0.760mm)" at 6834.64,759.51 h60
  text "NPTH" at 7471.21,759.51 h60
  text "Round" at 7730.35,759.51 h60
  text "Top Layer - Bottom Layer" at 8105.51,759.51 h60
  text "-" at 8829.84,759.51 h60
  text "-" at 9419.75,759.51 h60
  text "+/-2.00" at 10097.27,759.51 h60
  text "G" at 6176.79,749.52 h55.25
  text "2" at 6502.64,635.19 h60
  text "29.92mil (0.760mm)" at 6834.64,635.19 h60
  text "PTH" at 7471.21,635.19 h60
  text "Rectangle" at 7730.35,635.19 h60
  text "Top Layer - Bottom Layer" at 8105.51,635.19 h60
  text "120.08mil (3.050mm)" at 8829.84,635.19 h60
  text "120.08mil (3.050mm)" at 9419.75,635.19 h60
  text "15" at 6502.64,510.87 h60
  text "40.00mil (1.016mm)" at 6834.64,510.87 h60
  text "PTH" at 7471.21,510.87 h60
  text "Round" at 7730.35,510.87 h60
  text "Top Layer - Bottom Layer" at 8105.51,510.87 h60
  text "-" at 8829.84,510.87 h60
  text "-" at 9419.75,510.87 h60
  text "+/-3.00" at 10097.27,510.87 h60
  text "H" at 6176.79,500.88 h55.25
  text "12" at 6502.64,386.55 h60
  text "40.16mil (1.020mm)" at 6834.64,386.55 h60
  text "PTH" at 7471.21,386.55 h60
  text "Round" at 7730.35,386.55 h60
  text "Top Layer - Bottom Layer" at 8105.51,386.55 h60
  text "-" at 8829.84,386.55 h60
  text "-" at 9419.75,386.55 h60
  text "+/-3.00" at 10097.27,386.55 h60
  text "I" at 6186,376.56 h55.25
  text "1" at 6502.64,262.23 h60
  text "40.16mil (1.020mm)" at 6834.64,262.23 h60
  text "PTH" at 7471.21,262.23 h60
  text "Rectangle" at 7730.35,262.23 h60
  text "Top Layer - Bottom Layer" at 8105.51,262.23 h60
  text "140.16mil (3.560mm)" at 8829.84,262.23 h60
  text "140.16mil (3.560mm)" at 9419.75,262.23 h60
  text "10" at 6502.64,137.91 h60
  text "44.88mil (1.140mm)" at 6834.64,137.91 h60
  text "PTH" at 7471.21,137.91 h60
  text "Round" at 7730.35,137.91 h60
  text "Top Layer - Bottom Layer" at 8105.51,137.91 h60
  text "-" at 8829.84,137.91 h60
  text "-" at 9419.75,137.91 h60
  text "4" at 6502.64,13.59 h60
  text "70.87mil (1.800mm)" at 6834.64,13.59 h60
  text "PTH" at 7471.21,13.59 h60
  text "Round" at 7730.35,13.59 h60
  text "Top Layer - Bottom Layer" at 8105.51,13.59 h60
  text "-" at 8829.84,13.59 h60
  text "-" at 9419.75,13.59 h60
  text "+/-3.00" at 10097.27,13.59 h60
  text "K" at 6176.79,3.6 h55.25
  text "4" at 6502.64,-110.73 h60
  text "92.52mil (2.350mm)" at 6834.64,-110.73 h60
  text "NPTH" at 7471.21,-110.73 h60
  text "Round" at 7730.35,-110.73 h60
  text "Top Layer - Bottom Layer" at 8105.51,-110.73 h60
  text "-" at 8829.84,-110.73 h60
  text "-" at 9419.75,-110.73 h60
  text "+/-2.00" at 10097.27,-110.73 h60
  text "M" at 6176.79,-120.72 h55.25
  text "1" at 6502.64,-235.05 h60
  text "94.49mil (2.400mm)" at 6834.64,-235.05 h60
  text "NPTH" at 7471.21,-235.05 h60
  text "Round" at 7730.35,-235.05 h60
  text "Top Layer - Bottom Layer" at 8105.51,-235.05 h60
  text "-" at 8829.84,-235.05 h60
  text "-" at 9419.75,-235.05 h60
  text "+/-2.00" at 10097.27,-235.05 h60
  text "R" at 6176.79,-245.04 h55.25
  text "1" at 6502.64,-359.37 h60
  text "94.49mil (2.400mm)" at 6834.64,-359.37 h60
  text "NPTH" at 7471.21,-359.37 h60
  text "Slot" at 7730.35,-359.37 h60
  text "Top Layer - Bottom Layer" at 8105.51,-359.37 h60
  text "116.14mil (2.950mm)" at 8829.84,-359.37 h60
  text "21.65mil (0.550mm)" at 9419.75,-359.37 h60
  text "+/-2.00" at 10097.27,-359.37 h60
  text "N" at 6176.79,-369.36 h55.25
  text "4" at 6502.64,-483.69 h60
  text "125.98mil (3.200mm)" at 6834.64,-483.69 h60
  text "PTH" at 7471.21,-483.69 h60
  text "Round" at 7730.35,-483.69 h60
  text "Top Layer - Bottom Layer" at 8105.51,-483.69 h60
  text "-" at 8829.84,-483.69 h60
  text "-" at 9419.75,-483.69 h60
  text "+/-3.00" at 10097.27,-483.69 h60
  text "P" at 6176.79,-493.68 h55.25
  text "923 Total" at 6502.64,-608.01 h60
  text "Slot definitions :" at 6202.08,-695.03 h60
  text "Routed Path Length" at 6652.79,-695.03 h60
  text "= Calculated from tool start centre position to tool end centre position." at 7192.53,-695.03 h60
  text "Hole Length" at 6652.79,-744.76 h60
  text "= Routed Path Length + Tool Size = Slot length as defined in the PCB layout" at 6992.73,-744.76 h60
  text "FAB" at 366,-1069.49 h60
M17 Embedded Cavity:
  text ".Layer_Name" at 366,-1069.49 h60
M18 Embedded Assembly:
  text ".Layer_Name" at 366,-1069.49 h60
M19 Embedded Keepout:
  text ".Layer_Name" at 366,-1069.49 h60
